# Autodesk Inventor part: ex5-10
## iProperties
Shininess: 64.0
Length Units: 11272
Angle Units: 11279
Time Units: 11290
Mass Units: 11286
Length Display Precision: 3
Angle Display Precision: 2
Compacted: True
Part Number: ex5-10
Document SubType Name: Modeling
Created: 2003-11
Designer: Elise Moss
Cost Center: 0 lbmass
Authority: 0.97 in^3
Manufacturer: Standard
Standards Organization: Custom
Density: 0.0
Volumn: 0.0
Area: 0.0
PropertySet Name: Model Information
Control State: 0
Master: False
Checked Out: False
SaveDate: 2003-11-14
SaveTime: 19:17
TotalMass: 0 lbmass
TotalVolume: 0.97 in^3
Author: Elise Moss
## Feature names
1. Revolution1
2. Shell1
